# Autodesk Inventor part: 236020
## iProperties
Created: 2006-08
Part Number: 236020
Material: St vz
Description: Scheibe
Vendor: Autodesk Inc.
Document SubType Name: Modeling
Standard: DIN 125
Designer: I.Baliuc
Standards Organization: DIN
Language: de-DE
Size Designation: A 10.5
Categories: <MemberInstance Version="R10.0.0"><Categories><Category DisplayName="Schrauben" InternalName="e4da775c-781d-43d5-af7c-5136215cf5a6" Mnemonic="FSTN"><Category Di
Density: 7.85 g/cm^3
Mass: 3.57284 g
Surface Area: 6.46775 cm^2
Volume: 0.455138 cm^3
Abmessung: A 10
Author: T.Messerschmitt
Comments: DIN 125 - A 10.5
Revision Number: 236020
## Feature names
1. Körper [Extrusion]
